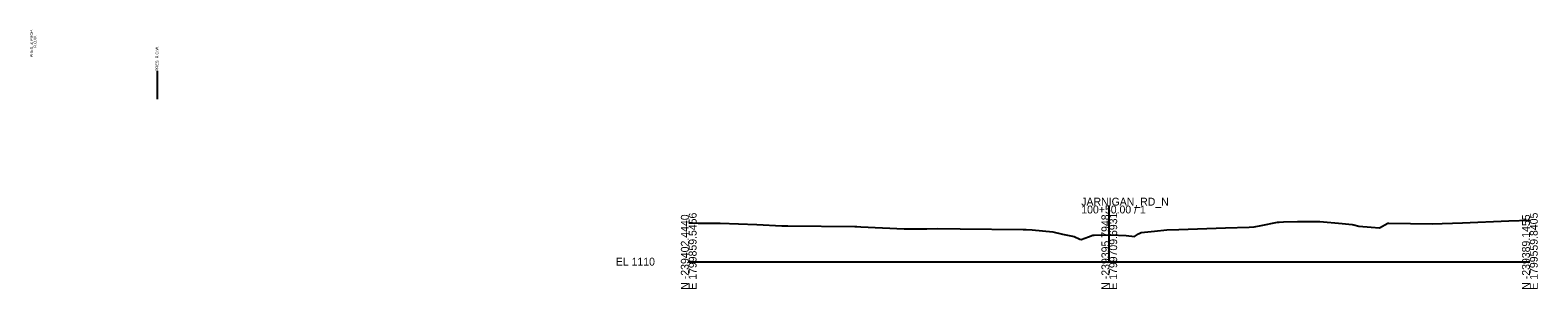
# Model space of a CAD drawing. Extents: x 214513 to 217151, y 214739 to 216780.
# Drawn here: x 214513 to 215051, y 214739 to 214831 of the extents above; entities that cross this region are included whole.
import ezdxf

# ---------------------------------------------------------------- set-up
doc = ezdxf.new("R2010")
doc.units = 0
for name, color, linetype in [('DESIGN - TRANSPORTATION - Text', 7, 'Continuous'), ('Section', 7, 'Continuous'), ('SURVEY - DTM GRAPHICS - Triangles', 7, 'Continuous'), ('SURVEY - PROPERTY - ROW Lines', 7, 'Continuous'), ('XSCell', 7, 'Continuous')]:
    doc.layers.add(name, color=color, linetype=linetype)

msp = doc.modelspace()

# ---------------------------------------------------------------- linework, layer by layer
at = {"layer": 'SURVEY - DTM GRAPHICS - Triangles'}
msp.add_lwpolyline([(214748.36, 214762.25), (214749.34, 214762.22), (214751.76, 214762.14), (214755.43, 214762.14), (214757.83, 214762.14), (214759.54, 214762.04), (214772.6, 214761.59), (214781.57, 214761.18), (214783.73, 214761.15), (214807.64, 214760.9), (214808.3, 214760.91), (214809.74, 214760.83), (214825.25, 214760.02), (214833.33, 214760.05), (214836.93, 214760.16), (214845.17, 214760.07), (214867.68, 214759.86), (214868.73, 214759.84), (214870.87, 214759.73), (214878.18, 214758.98), (214881.68, 214758.22), (214885.8, 214757.35), (214887.84, 214756.4), (214888.27, 214756.22), (214890.94, 214757.2), (214892.43, 214757.76), (214892.96, 214757.76), (214898.83, 214757.91), (214904.32, 214757.74), (214904.39, 214757.74), (214904.43, 214757.74), (214907.4, 214757.38), (214908.76, 214758.23), (214909.73, 214758.78), (214914.49, 214759.21), (214918.91, 214759.71), (214923.17, 214759.78), (214939.78, 214760.4), (214948.27, 214760.7), (214950, 214760.75), (214952.58, 214761.25), (214958.32, 214762.39), (214958.99, 214762.45), (214960.52, 214762.6), (214965.46, 214762.63), (214973.5, 214762.66), (214981.45, 214761.94), (214984.93, 214761.63), (214985.52, 214761.46), (214987.35, 214761.05), (214991.72, 214760.68), (214994.74, 214760.38), (214997.74, 214762.06), (214997.8, 214762.1), (214998, 214762.1), (215013.51, 214761.86), (215024.37, 214762.15), (215040.88, 214762.92), (215048.36, 214763.17)], dxfattribs=at)
at = {"layer": 'SURVEY - PROPERTY - ROW Lines'}
msp.add_lwpolyline([(214558.72, 214816.31), (214558.72, 214806.31)], dxfattribs=at)
at = {"layer": 'XSCell'}
for p, q in [((214898.36, 214748.36), (214898.36, 214768.36)), ((214748.36, 214748.36), (214898.36, 214748.36)), ((214898.36, 214748.36), (215048.36, 214748.36))]:
    msp.add_line(p, q, dxfattribs=at)

# ---------------------------------------------------------------- texts
at = {"layer": 'DESIGN - TRANSPORTATION - Text'}
for s, p in [('PRES. & PROP. ', (214514.49, 214821.23)), ('R.O.W.', (214515.74, 214824.64)), ('PRES. R.O.W.', (214559.22, 214816.31))]:
    msp.add_text(s, height=1, rotation=90, dxfattribs=at).set_placement(p)
at = {"layer": 'Section'}
msp.add_text('-', height=0.0001, dxfattribs=at).set_placement((214748.36, 214748.36))
at = {"layer": 'XSCell'}
for s, p in [('JARNIGAN_RD_N', (214888.36, 214768.36)), ('100+50.00 / 1', (214888.36, 214765.56)), ('EL 1110', (214722.36, 214746.96))]:
    msp.add_text(s, height=2.8, dxfattribs=at).set_placement(p)
for s, p in [('N -239402.4440', (214748.36, 214738.36)), ('E 1799859.5456', (214751.16, 214738.36)), ('N -239395.7948', (214898.36, 214738.36)), ('E 1799709.6931', (214901.16, 214738.36)), ('N -239389.1455', (215048.36, 214738.36)), ('E 1799559.8405', (215051.16, 214738.36))]:
    msp.add_text(s, height=2.8, rotation=90, dxfattribs=at).set_placement(p)

doc.saveas('drawing.dxf')
